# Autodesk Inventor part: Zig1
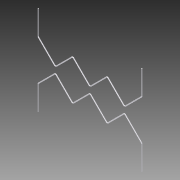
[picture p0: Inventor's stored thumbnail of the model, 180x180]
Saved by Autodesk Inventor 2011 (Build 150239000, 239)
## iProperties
Created: 2014-02
Part Number: Zig1
Document SubType Name: Modeling
Designer: Evgeny
Density: 1 g/cm^3
Author: Evgeny
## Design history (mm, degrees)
sketch "Эскиз1"
  geometry: L1 (0, 0)-(0, 100.929); L2 (1.464, 104.464)-(69.296, 172.296); L3 (76.368, 172.296)-(142.128, 106.536); L4 (149.2, 106.536)-(214.96, 172.296); L5 (222.032, 172.296)-(287.792, 106.536); L6 (294.864, 106.536)-(360.624, 172.296); L7 (367.696, 172.296)-(435.528, 104.464); L8 (436.992, 100.929)-(436.992, 0); L9 (436.992, 376.664)-(436.992, 275.735); L10 (435.528, 272.2)-(367.696, 204.368); L11 (360.624, 204.368)-(294.864, 270.128); L12 (287.792, 270.128)-(222.032, 204.368); L13 (214.96, 204.368)-(149.2, 270.128); L14 (142.128, 270.128)-(76.368, 204.368); L15 (69.296, 204.368)-(1.464, 272.2); L16 (0, 275.735)-(0, 376.664); A1 r 5 centre (5, 100.929) between (1.464, 104.464) and (0, 100.929); A2 r 5 centre (72.832, 168.761) between (76.368, 172.296) and (69.296, 172.296); A3 r 5 centre (145.664, 110.071) between (142.128, 106.536) and (149.2, 106.536); A4 r 5 centre (218.496, 168.761) between (222.032, 172.296) and (214.96, 172.296); A5 r 5 centre (291.328, 110.071) between (287.792, 106.536) and (294.864, 106.536); A6 r 5 centre (364.16, 168.761) between (367.696, 172.296) and (360.624, 172.296); A7 r 5 centre (431.992, 100.929) between (436.992, 100.929) and (435.528, 104.464); A8 r 5 centre (431.992, 275.735) between (435.528, 272.2) and (436.992, 275.735); A9 r 5 centre (364.16, 207.903) between (360.624, 204.368) and (367.696, 204.368); A10 r 5 centre (291.328, 266.593) between (294.864, 270.128) and (287.792, 270.128); A11 r 5 centre (218.496, 207.903) between (214.96, 204.368) and (222.032, 204.368); A12 r 5 centre (145.664, 266.593) between (149.2, 270.128) and (142.128, 270.128); A13 r 5 centre (72.832, 207.903) between (69.296, 204.368) and (76.368, 204.368); A14 r 5 centre (5, 275.735) between (0, 275.735) and (1.464, 272.2); 16 further points
  constraints: 32 end point, 28 point on circle, 28 point on line, 28 tangent, 14 centre point, 12 equal radius, 10 perpendicular, 2 parallel, 1 vertical
  dimensions: "d0" = 103 distance of L1.start point (0, 103); "d1" = 103 distance of point (0, 103) point (72.832, 175.832); "d2" = 103 distance of point (72.832, 175.832) point (145.664, 103); "d3" = 103 distance of point (145.664, 103) point (218.496, 175.832); "d4" = 103 distance of point (218.496, 175.832) point (291.328, 103); "d5" = 103 distance of point (291.328, 103) point (364.16, 175.832); "d6" = 103 distance of point (364.16, 175.832) point (436.992, 103); "d7" = 103 distance of point (436.992, 103) L8.end; "d9" = 135 deg angle of L2 L1; "d10" = 135 deg angle of L8 L7 (derived); "d12" = 5 radius of A1; "d13" = 12.5 distance of point (218.496, 188.332) point (218.496, 175.832); "d14" = 103 distance of L9.start point (436.992, 273.664); "d15" = 103 distance of point (436.992, 273.664) point (364.16, 200.832); "d16" = 103 distance of point (364.16, 200.832) point (291.328, 273.664); "d17" = 103 distance of point (291.328, 273.664) point (218.496, 200.832); "d18" = 103 distance of point (218.496, 200.832) point (145.664, 273.664); "d19" = 103 distance of point (145.664, 273.664) point (72.832, 200.832); "d20" = 103 distance of point (72.832, 200.832) point (0, 273.664); "d21" = 103 distance of point (0, 273.664) L16.end; "d22" = 135 deg angle of L10 L9; "d23" = 135 deg angle of L16 L15 (derived); "d24" = 5 radius of A8; "d25" = 12.5 distance of point (218.496, 188.332) point (218.496, 200.832)
sketch "Эскиз2"
  geometry: C1 r 2 at (0, 0); 1 further point
  constraints: 1 centre point, 1 coincident
  dimensions: "d11" = 4 diameter of C1
feature "Сдвиг1" sketch "Эскиз2" dims "d26" = 0
node "РабПлоскость1"
sketch "Эскиз3"
  geometry: C1 r 2 at (0, 0); 1 further point
  constraints: 1 centre point, 1 coincident
  dimensions: "d27" = 4 diameter of C1
feature "Сдвиг2" sketch "Эскиз3" dims "d28" = 0
node "Твердое тело1"
